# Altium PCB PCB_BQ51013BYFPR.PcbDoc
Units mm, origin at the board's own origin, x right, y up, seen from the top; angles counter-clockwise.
Board outline 45 x 20 mm, 2 copper layers (Top Layer, Bottom Layer); 61 components, 48 nets, 200 pads, 50 vias.
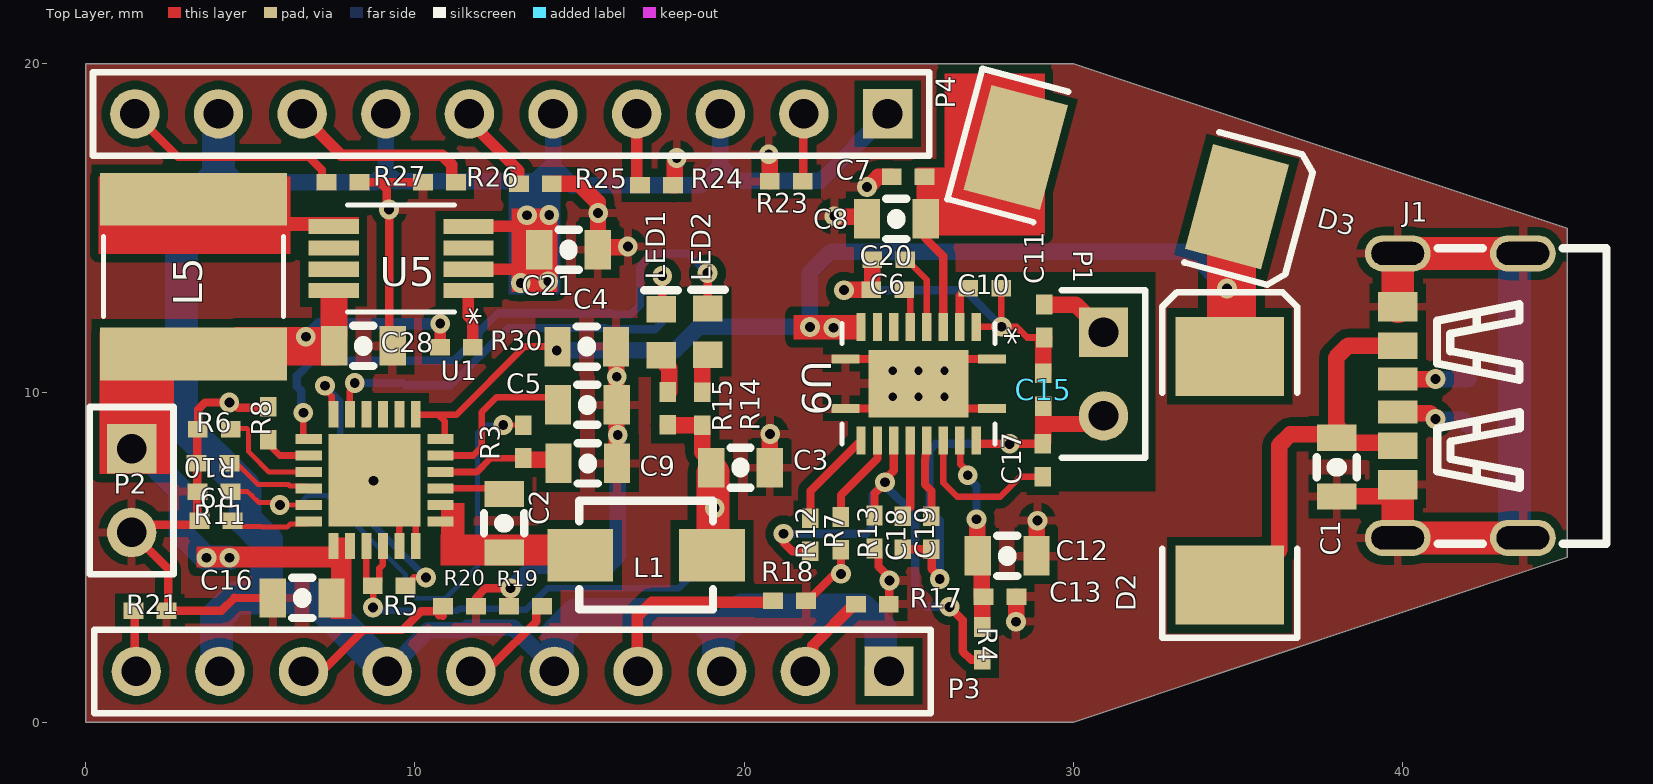
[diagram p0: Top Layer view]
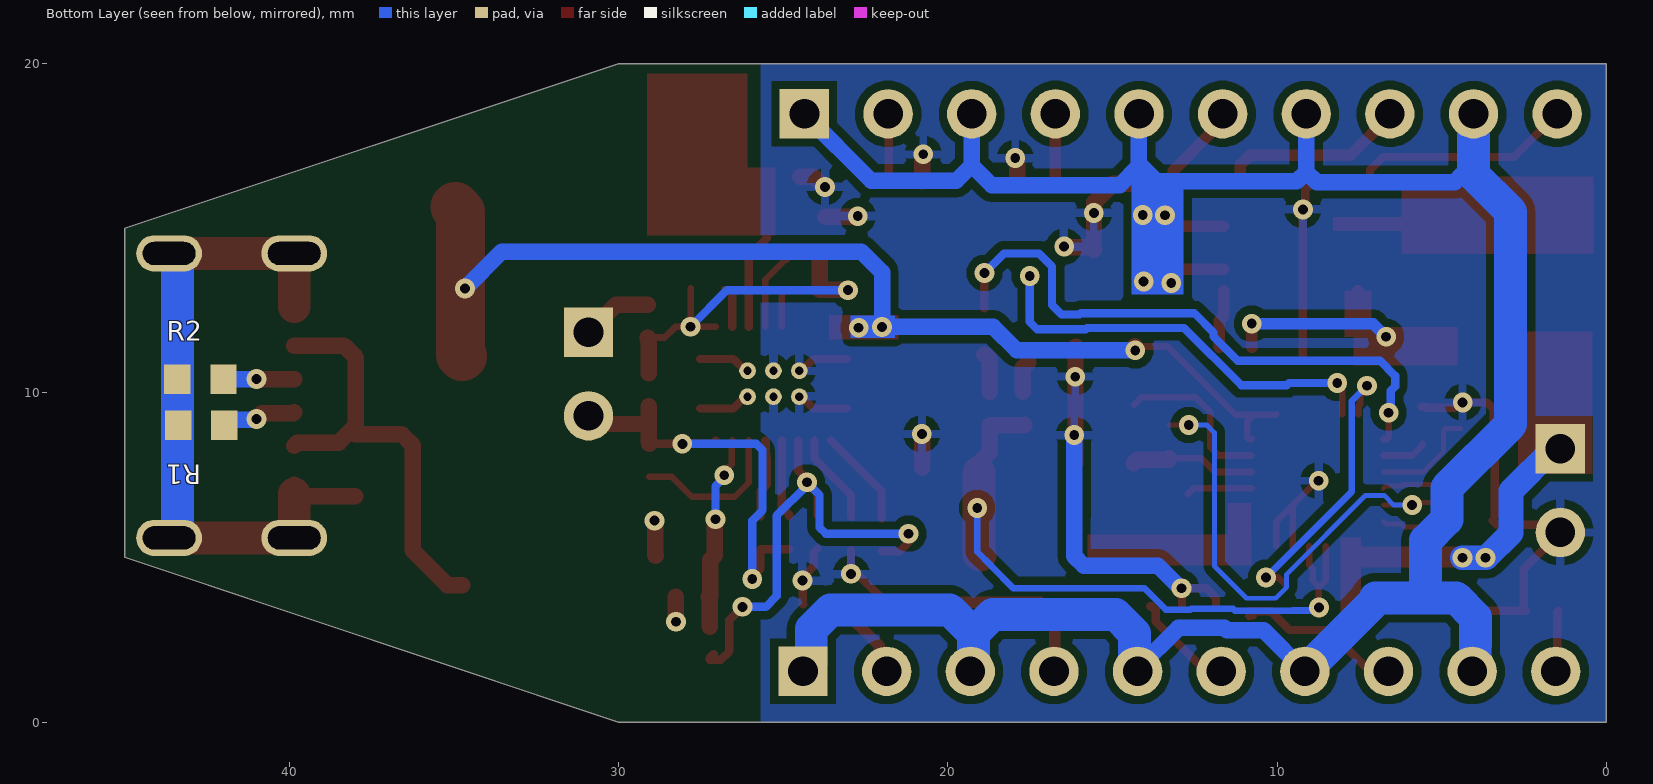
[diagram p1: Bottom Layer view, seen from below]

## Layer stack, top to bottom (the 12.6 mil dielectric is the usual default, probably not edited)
Top Solder: solder mask 0.0102, Solder Resist, Dk 3.5
Top Layer: signal copper 0.0356
Dielectric 1: dielectric 0.32, FR-4, Dk 4.8
Bottom Layer: signal copper 0.0356
Bottom Solder: solder mask 0.0102, Solder Resist, Dk 3.5

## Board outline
0,0 30,0 45,5 45,15 30,20 0,20

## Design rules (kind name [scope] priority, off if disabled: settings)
Clearance U1 [InComponent('U1')] p1: gap=0.254 ignorepadtopadclearanceinfootprint=FALSE except(0: Arc-Hole Track-Hole SMDPad-Hole THPad-Hole Via-Hole Fill-Hole Poly-Hole Region-Hole Text-Hole; 0.18: Arc-Arc Arc-Track Arc-SMDPad Track-Track Track-SMDPad SMDPad-SMDPad)
Clearance U5 [InComponent('U5')] p2: gap=0.254 ignorepadtopadclearanceinfootprint=FALSE except(0: Arc-Hole Track-Hole SMDPad-Hole THPad-Hole Via-Hole Fill-Hole Poly-Hole Region-Hole Text-Hole; 0.18: Arc-Arc Arc-Track Arc-SMDPad Arc-THPad Track-Track Track-SMDPad Track-THPad SMDPad-SMDPad SMDPad-THPad THPad-THPad; 0.2: Arc-Via Track-Via)
Clearance U2 [InComponent('U2')] p3: gap=0.254 ignorepadtopadclearanceinfootprint=FALSE except(0: Arc-Hole Track-Hole SMDPad-Hole THPad-Hole Via-Hole Fill-Hole Poly-Hole Region-Hole Text-Hole; 0.15: Arc-Arc Arc-Track Arc-SMDPad Arc-THPad Track-Track Track-SMDPad Track-THPad SMDPad-SMDPad SMDPad-THPad SMDPad-Via SMDPad-Fill SMDPad-Poly SMDPad-Region THPad-THPad Via-Via Via-Fill Via-Poly Via-Region Via-Text)
Clearance [All] p4: gap=0.254 ignorepadtopadclearanceinfootprint=FALSE except(0: Arc-Hole Track-Hole SMDPad-Hole THPad-Hole Via-Hole Fill-Hole Poly-Hole Region-Hole Text-Hole; 0.2: Arc-Arc Arc-Track Arc-SMDPad Track-Track Track-SMDPad SMDPad-SMDPad)
MinimumSolderMaskSliver USB-C-SMD_TYPE-C-USB-13 [HasFootprint('USB-C-SMD_TYPE-C-USB-13')] p1: minsoldermaskwidth=0
MinimumSolderMaskSliver RHL20_2P05X3P05 [HasFootprint('RHL20_2P05X3P05')] p2: minsoldermaskwidth=0
MinimumSolderMaskSliver [All] p3: minsoldermaskwidth=0.1
PolygonConnect [All] p1: connectstyle=Relief reliefconductorwidth=0.254 reliefentries=4 polygonreliefangle="90 Angle" airgapwidth=0.254
RoutingVias [All] p1: holewidth=0.711 width=1.27 viastyle="Through Hole" minholewidth=0.3 minwidth=0.6 maxholewidth=0.711 maxwidth=1.27
SilkToSilkClearance [All] p1: silktosilkclearance=0.1
SilkToSolderMaskClearance 0805-CAP [HasFootprint('0805-CAP')] p1: minsilkscreentomaskgap=0 clearancetoexposedcopper=TRUE
SilkToSolderMaskClearance 1608[0603]_LED [HasFootprint('1608[0603]_LED')] p2: minsilkscreentomaskgap=0 clearancetoexposedcopper=TRUE
SilkToSolderMaskClearance 0402-A [HasFootprint('0402-A')] p3: minsilkscreentomaskgap=0 clearancetoexposedcopper=TRUE
SilkToSolderMaskClearance [IsPad] p4: minsilkscreentomaskgap=0.1 clearancetoexposedcopper=TRUE
SolderMaskExpansion [All] p1: expansion=0.102 istentingtop=FALSE
Width [All] p1: maxlimit=1.5 minlimit=0.15 preferedwidth=0.254
27 further rules are at their usual default settings.

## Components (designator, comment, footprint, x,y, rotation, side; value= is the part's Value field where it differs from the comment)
C1 "Cap" 0805-CAP 38.025,7.76 r270 top value=1uF
C2 "Cap" 0805-CAP 12.737,6.056 r270 top value=47nF/25V
C3 "Cap" 0805-CAP 19.91,7.7 r180 top value=10uF/25V
C4 "Cap" 0805-CAP 15.24,11.38 r180 top value=1uF/25V
C5 "Cap" 0805-CAP 15.22,9.66 r0 top value=10uF/25V
C6 "Cap" 0402-A 24.361,13.128 r0 top value=22nF/25V
C7 "Cap" 0402-A 24.982,16.564 r0 top value=0.1uF/16V
C8 "Cap" 0805-CAP 24.605,15.306 r0 top value=10uF/16V
C9 "Cap" 0805-CAP 15.27,7.83 r180 top value=4.7uF/10V
C10 "Cap" 0402-A 27.31,13.17 r180 top value=10nF/25V
C11 "Cap" 0402-A 29.11,12.18 r270 top value=0.25uF/25V
C12 "Cap" 0805-CAP 28.01,5.02 r180 top value=10uF/16V
C13 "Cap" 0402-A 27.77,3.81 r180 top value=0.1uF/16V
C15 "Cap" 0402-A 29.085,10.092 r90 top value=2.5nF/25V
C16 "Cap" 0805-CAP 6.598,3.743 r180 top value=10uF/16V
C17 "Cap" 0402-A 29.07,7.95 r270 top value=10nF/25V
C18 "Cap" 0402-A 24.82,5.75 r90 top value=22nF/25V
C19 "Cap" 0402-A 25.691,5.749 r90 top value=0.47uF/25V
C20 "Cap" 0402-A 24.392,14.042 r0 top value=0.47uF/25V
C21 "Cap" 0805-CAP 14.65,14.37 r0 top value=10uF/25V
C28 "Cap" 0805-CAP 8.457,11.397 r180 top value=10uF/25V
D2 "SK56A-LTP" SMC 34.752,7.632 r90 top
D3 "SK56A-LTP" SMC 31.612,16.551 r345 top
J1 "USB 3.1 C 6PF COPY" USB-C-SMD_TYPE-C-USB-13 42,10 r90 top
L1 "1uH" IND-SMD_L4.1-W3.2 17.2,5.07 r0 top
L5 "4.7uH" IND_BOURNS_SRN50 3.28,13.53 r90 top value=SRN5020-4R7M
LED1 "LED0" 1608[0603]_LED 17.48,11.842 r90 top
LED2 "LED0" 1608[0603]_LED 18.9,11.86 r90 top
P1 "Header 2" HDR1X2 30.916,11.84 r270 top
P2 "Header 2" HDR1X2 1.401,8.3 r270 top
P3 "Header 10" HDR1X10 24.4,1.54 r180 top
P4 "Header 10" HDR1X10 24.358,18.472 r180 top
R1 "Res1" 1608[0603] 42.68,9.019 r0 bottom value=5.1k
R2 "Res1" 1608[0603] 42.702,10.407 r180 bottom value=5.1k
R3 "Res1" 0402-A 13.288,8.517 r270 top value=10k
R4 "Res1" 0402-A 27.24,2.39 r270 top value=20K
R5 "Res1" 0402-A 9.22,4.14 r180 top value=10K
R6 "Res1" 0402-A 3.908,8.893 r180 top value=10K
R7 "Res1" 0402-A 22.94,5.73 r270 top value=10k
R8 "Res1" 0402-A 5.548,9.074 r90 top value=158R
R9 "Res1" 0402-A 3.9,7 r0 top value=10k
R10 "Res1" 0402-A 3.87,7.855 r180 top value=221R
R11 "Res1" 0402-A 3.96,6.12 r180 top value=10K
R12 "Res1" 0402-A 22.003,5.689 r270 top value=66R
R13 "Res1" 0402-A 23.961,5.772 r270 top value=196R
R14 "Res1" 0402-A 18.726,9.517 r90 top value=10K
R15 "Res1" 0402-A 17.683,9.528 r90 top value=2.21K
R17 "Res1" 0402-A 23.896,3.577 r180 top value=1K
R18 "Res1" 0402-A 21.38,3.68 r180 top value=1K
R19 "Res1" 0402-A 13.364,3.514 r0 top value=1K
R20 "Res1" 0402-A 11.357,3.514 r180 top value=1K
R21 "Res1" 0402-A 1.957,3.386 r180 top value=1K
R23 "Res1" 0402-A 21.28,16.42 r0 top value=1K
R24 "Res1" 0402-A 17.34,16.3 r180 top value=1K
R25 "Res1" 0402-A 13.661,16.344 r180 top value=1K
R26 "Res1" 0402-A 10.75,16.39 r0 top value=1K
R27 "Res1" 0402-A 7.82,16.39 r180 top value=1K
R30 "Res1" 0402-A 11.263,11.378 r0 top value="1M Ohm"
U1 "BQ25616JRTWR" QFN50P400X400X80 8.772,7.354 r270 top
U5 "MCP1643T-I/MS" MSOP8_MC_MCH 9.585,14.078 r180 top
U9 "BQ51013BRHLR" RHL20_2P05X3P05 25.298,10.277 r270 top

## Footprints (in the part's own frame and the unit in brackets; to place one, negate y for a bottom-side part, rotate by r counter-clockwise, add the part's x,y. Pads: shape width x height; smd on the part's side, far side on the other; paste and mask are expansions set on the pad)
0402-A [mm] "Chip Inductor, Body 1.0x0.5mm, IPC High Density"
  rect 0.6x0.5 smd: 1(-0.5,0) 2(0.5,0)
  body extent -0.55,-0.3 0.55,0.3, height 0.55
0805-CAP [mil]
  rect 31.5x47.2 smd: 1(-34.25,-1) 2(35.75,-1)
  silkscreen extent -11,-25 13,23
1608[0603] [mm] "Chip Capacitor, Body 1.6x0.8mm, IPC High Density"
  rect 0.8x0.9 smd: 1(-0.7,0) 2(0.7,0)
  body extent -0.87,-0.48 0.87,0.48, height 1.3
1608[0603]_LED [mm] "Chip Capacitor, Body 1.6x0.8mm, IPC High Density"
  rect 0.8x0.9 smd: 1(-0.7,0) 2(0.7,0)
  silkscreen extent 1.27,-0.51 1.27,0.51, body extent -0.87,-0.48 0.87,0.48, height 1.3
HDR1X2 [mm] "Connector; Header; 2 Position"
  rect 1.5x1.5 hole 0.9: 1(0,0)
  round 1.5 hole 0.9: 2(2.54,0)
  silkscreen extent -1.27,-1.27 3.81,1.27
HDR1X10 [mm] "Connector; Header; 10 Position"
  rect 1.5x1.5 hole 0.9: 1(0,0)
  round 1.5 hole 0.9: 2(2.54,0) 3(5.08,0) 4(7.62,0) 5(10.16,0) 6(12.7,0) 7(15.24,0) 8(17.78,0) 9(20.32,0) 10(22.86,0)
  silkscreen extent -1.27,-1.27 24.13,1.27
IND-SMD_L4.1-W3.2 [mm]
  rect 2x1.6 smd: 1(-2.175,0) 2(1.825,0)
  silkscreen extent -2.21,-1.65 1.86,1.65
IND_BOURNS_SRN50 [mil]
  rect 63x224 smd: 1(-92.5,0) 2(92.5,0)
  silkscreen extent -48,-108 48,108
MSOP8_MC_MCH [mil]
  rect 60x18 smd: 1(-80.5,38.39) 2(-80.5,12.8) 3(-80.5,-12.8) 4(-80.5,-38.39) 5(80.5,-38.39) 6(80.5,-12.8) 7(80.5,12.8) 8(80.5,38.39)
  silkscreen extent -64,-64 64,64
QFN50P400X400X80 [mil]
  rect 31.5x11.81 smd: 1(-78.43,49.53) 2(-78.43,29.85) 3(-78.43,10.15) 4(-78.43,-9.52) 5(-78.43,-29.21) 6(-78.43,-48.89) 13(79.05,-48.89) 14(79.05,-29.21) 15(79.05,-9.52) 16(79.05,10.15) 17(79.05,29.85) 18(79.05,49.53)
  rect 11.81x31.5 smd: 7(-48.9,-78.42) 8(-29.22,-78.42) 9(-9.53,-78.42) 10(10.15,-78.42) 11(29.84,-78.42) 12(49.52,-78.42) 19(49.52,79.06) 20(29.84,79.06) 21(10.15,79.06) 22(-9.53,79.06) 23(-29.22,79.06) 24(-48.9,79.06)
  rect 110.24x110.24 smd: 25(0.31,0.32)
RHL20_2P05X3P05 [mm]
  rect 0.28x0.85 smd: 1(-0.75,2.225) 10(-0.75,-2.225) 11(0.75,-2.225) 20(0.75,2.225)
  rect 0.85x0.28 smd: 2(-1.725,1.75) 3(-1.725,1.25) 4(-1.725,0.75) 5(-1.725,0.25) 6(-1.725,-0.25) 7(-1.725,-0.75) 8(-1.725,-1.25) 9(-1.725,-1.75) 12(1.725,-1.75) 13(1.725,-1.25) 14(1.725,-0.75) 15(1.725,-0.25) 16(1.725,0.25) 17(1.725,0.75) 18(1.725,1.25) 19(1.725,1.75)
  rect 2.05x3.05 smd: 21(0,0)
  round 0.508 hole 0.254 mask-25.4: 22(-0.394,-0.787) 23(-0.394,0) 24(-0.394,0.787) 25(0.394,-0.787) 26(0.394,0) 27(0.394,0.787)
  silkscreen extent -1.83,-2.32 1.83,2.32
SMC [mm] "DO-214-AB/SMC; 2 C-Bend Leads; Body 7.9 x 5.9 mm, inc. leads (LxW)"
  rect 2.4x3.3 smd: 1(-3.475,0) 2(3.475,0)
  silkscreen extent -5.07,-2.05 5.43,2.05
USB-C-SMD_TYPE-C-USB-13 [mm]
  oval 1.1x2 hole 0.7 slot 1.6 at 90 deg: 0(-4.407,-1.652) 0(-4.407,2.148) 0(4.233,-1.652) 0(4.233,2.148)
  rect 0.7x1.2 smd: A5(-0.587,2.146) B5(0.413,2.146)
  rect 0.8x1.2 smd: A9(-1.607,2.148) B9(1.433,2.15)
  rect 0.9x1.2 smd: A12(-2.787,2.148) B12(2.613,2.148)
  silkscreen extent -4.59,-4.19 4.39,0.95

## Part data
C1 C2 C3 C4 C5 C6 C7 C8 C9 C10 C11 C12 C13 C15 C16 C17 C18 C19 C20 C21 C28: "Capacitor"
D2 D3: library part Diode, "DIODE SCHOTTKY 5A 60V SMA"
L1: library part Inductor
L5: library part SRN5020-4R7M, Mfr_Name="Bourns Electronics"
P1 P2: "Header, 2-Pin"
P3 P4: "Header, 10-Pin"
R1 R2 R3 R4 R5 R6 R7 R8 R9 R10 R11 R12 R13 R14 R15 R17 R18 R19 R20 R21 R23 R24 R25 R26 R27 R30: "Resistor"
U5: Mfr_Name=Microchip
U9: Mfr_Name="Texas Instruments"

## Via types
v1: diameter 0.6, hole 0.3, Top Layer to Bottom Layer, tented both sides, 39 vias
v2: diameter 0.6, hole 0.3, Top Layer to Bottom Layer, 11 vias

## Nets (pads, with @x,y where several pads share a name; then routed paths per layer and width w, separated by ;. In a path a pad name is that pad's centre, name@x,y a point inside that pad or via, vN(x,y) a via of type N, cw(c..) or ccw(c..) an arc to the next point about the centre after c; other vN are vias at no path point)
+5: C21.1 P3.1 P3.3 P3.5 P3.7 P3.9 P4.1 P4.3 P4.5 P4.7 P4.9 U5.2 U5.4 | length 77.2
  Top Layer w0.35: U5.2 13.388,13.753 13.78,14.145 C21.1 13.78,14.544 13.271,15.053 U5.4
  Bottom Layer w0.5: 4.384,16.626 4.61,16.4 8.805,16.4 9.118,16.713 ; P4.7 9.118,16.713 ; P3.7 10.414,2.794 11.534,2.794 11.6,2.86 13,2.86 14.24,1.62 P3.5 ; P4.5 14.198,16.958 ; P4.3 19.278,16.912 ; P4.1 22.326,16.44 19.75,16.44 19.278,16.912 ; 9.118,16.713 9.411,16.42 13.66,16.42 14.198,16.958 ; 14.198,16.958 14.198,16.892 14.784,16.306 18.672,16.306 19.278,16.912
  Bottom Layer w1: P4.9 4.038,16.626 2.911,15.499 2.911,9.05 4.848,7.113 4.848,6.152 5.49,5.51 5.49,3.77 ; P3.9 3.984,1.636 3.984,2.351 3.98,2.356 3.98,3.184 4.566,3.77 5.49,3.77 ; P3.7 7.019,3.681 7.019,3.77 5.49,3.77 ; P3.5 14.336,1.636 14.336,2.696 14.91,3.27 18.639,3.27 19.224,2.684 ; P3.3 19.224,1.636 19.224,2.684 ; P3.1 24.15,1.79 24.15,2.824 23.564,3.41 19.95,3.41 19.224,2.684
  other v1: 13.217,13.335
  other v2: 14.056,13.377 13.405,15.392 14.082,15.397
+VBAT: C16.1 C28.2 L5.1 P2.1 R30.1 U1.13 U1.14 U5.8 | length 15.2
  Top Layer w0.35: v2(3.67,4.99) 3.68,5 4.36,5 v2@4.37,5.01 ; v2(4.37,4.99) 5.767,4.99 5.787,5.01 7.634,5.01 U1.13@7.634,5.023 ; v1(6.691,11.702) 6.973,11.42 7.1,11.42 C28.2@7.505,11.825 ; U5.8 U5.8@7.549,13.094 ; R30.1 10.768,11.383 10.768,12.096 v1(10.772,12.101)
  Bottom Layer w0.35: v1(6.691,11.702) 7.089,12.101 v1(10.772,12.101)
  Bottom Layer w0.75: P2.1 1.62,8.3 2.901,7.019 2.901,5.739 3.65,4.99 v2(3.67,4.99) v2(4.37,4.99)
C_VCC: C4.2 D2.2 D3.2 U1.1 U1.24 U9.9 | length 33.9
  Top Layer w0.2: U1.1 10.046,9.33 10.72,9.33 ; U1.24 10.86,8.596 10.91,8.646 10.91,9.14 10.72,9.33 ; C4.2 C4.2 13.335,11.405 11.26,9.33 10.72,9.33
  Top Layer w0.5: v1(14.31,11.29) 14.33,11.31 C4.2 C4.2@14.33,11.407
  Top Layer w1.5: D2.2 34.802,11.157 34.802,15.485 D3.2
  Bottom Layer w0.5: v1(14.31,11.29) 15.801,11.29 16.467,11.29 17.912,11.29 18.623,12.001 21.999,12.001 v1(22,12) 22,13.66 22.63,14.29 33.55,14.29 v1(34.67,13.17)
  other v1: 22.71,11.977
FOD: R4.2 R12.2 R13.1 U9.14 | length 15.4
  Top Layer w0.25: v1(21.2,5.72) 21.2,5.45 21.461,5.189 R12.2 ; R13.1 23.961,6.947 24.282,7.268 v1(24.282,7.282) ; v1@24.28,7.35 24.28,7.375 24.548,7.643 U9.14 ; v1(26.24,3.5) 26.64,3.1 26.64,2.15 26.9,1.89 R4.2 27.24,1.94 R4.2@27.115,2.065
  Bottom Layer w0.25: v1(21.2,5.72) 23.71,5.72 23.9,5.91 23.9,6.9 v1(24.282,7.282) 24.282,7.187 25.2,6.269 25.2,3.83 25.53,3.5 v1(26.24,3.5)
GND: C1.2 C3.1 C4.1 C5.2 C7.1 C8.1 C9.1 C12.1 C13.1 C16.2 C21.2 C28.1 J1.0 J1.A12 J1.B12 P2.2 R1.2 R2.1 R6.2 R7.2 R8.2 R9.1 R10.2 R11.2 R13.2 R17.1 R18.1 R19.1 R20.1 R21.1 R23.1 R24.1 R25.1 R26.1 R27.1 U1.17 U1.18 U1.25 U9.1 U9.10 U9.11 U9.20 U9.21 U9.22 U9.23 U9.24 U9.25 U9.26 U9.27 | length 80.8
  Top Layer w0.2: U1.25 U1.25@9.53,6.596 ; U1.17 U1.25@9.53,6.596 ; U1.18 10.03,6.096 U1.25@9.53,6.596
  Top Layer w0.25: v1@22.94,4.503 R7.2@22.94,5.23 ; U9.11 24.085,9.527 24.441,9.884 U9.25 ; U9.10 24.085,11.027 24.441,10.671 U9.22 ; R13.2 24.086,5.147 24.086,4.727 24.417,4.396 v2(24.417,4.302) ; U9.27 26.156,9.884 26.512,9.527 U9.20 ; U9.24 26.156,10.671 26.512,11.027 U9.1
  Top Layer w0.254: R11.2@3.389,6.261 3.389,8.031 3.394,8.036 3.394,8.988 3.422,9.016 3.422,9.497 3.633,9.707 v1(4.367,9.707) 4.461,9.707 4.626,9.542 5.484,9.542 5.515,9.573 R8.2@5.607,9.573 ; R11.2 3.337,5.997 1.638,5.997 P2.2 2.512,4.65 2.512,3.441 R21.1 4.13,3.386 4.518,3.774 4.524,3.768 C16.2 ; R27.1 8.93,16.39 ; C28.1@9.218,11.123 v1(9.218,15.564) 9.152,15.63 9.152,16.168 8.93,16.39 ; R26.1 8.93,16.39 ; R20.1 11.858,3.77 12.153,4.065 v2(12.909,4.065) 12.893,4.05 R19.1@12.893,3.514 ; R18.1 21.93,3.68 v1@22.702,4.452 ; R17.1 24.407,3.588 24.407,4.291 v2(24.417,4.302)
  Top Layer w0.5: R25.1 14.996,16.344 15.55,15.79 15.55,15.482 v1(15.569,15.463) 15.564,15.457 C21.2@15.564,14.35 ; C21.2 C21.2@15.564,14.35 ; C4.1 16.125,11.39 16.125,7.87 C9.1 ; v1(16.47,14.44) 16.451,14.421 15.634,14.421 C21.2@15.564,14.35 ; R24.1 17.89,16.3 17.89,17.036 17.955,17.101 v1(17.955,17.128) ; v1(20.75,17.244) 20.75,17.217 20.78,17.187 R23.1 ; C3.1 20.786,7.732 20.786,8.746 v1(20.793,8.753) ; v1(22.738,15.365) 22.75,15.352 23.71,15.352 C8.1@23.722,15.339 ; v1(23.735,16.252) 23.762,16.252 24.074,16.564 C7.1 ; v1(28.261,3.046) 28.265,3.051 28.265,3.81 C13.1 ; C12.1 28.894,5.06 28.894,6.103 v1(28.909,6.117) ; C1.2 39.774,6.852 J1.A12@39.852,6.93 ; J1.A12@39.729,7.09 J1.A12
  Top Layer w1: J1.0@39.375,14.233 39.852,14.233 J1.0@43.652,14.233 ; J1.0@39.852,5.593 J1.A12@39.852,6.93 ; J1.B12 J1.0@39.852,14.233 ; J1.0@39.852,5.593 J1.0@43.652,5.593
  Bottom Layer w0.5: v2(12.909,4.065) 12.936,4.065 13.62,4.75 15.877,4.75 16.17,5.043 16.17,6.22 16.164,6.226 v2(16.164,8.716)
  Bottom Layer w1: J1.0@43.652,5.593 43.448,5.593 43.402,5.639 R2.1 43.402,14.187 43.448,14.233 J1.0@43.652,14.233
  other v1: 22.941,4.502
  other v2: 8.74,7.33 16.134,10.486
NetC1_1: C1.1 D2.1 J1.A9 J1.B9 | length 13.2
  Top Layer w0.5: D2.1 35.202,4.157 36.26,5.216 36.26,5.645 36.25,5.655 36.25,8.4 36.59,8.74 C1.1@38.005,8.74 ; J1.B9 38.343,11.433 37.98,11.07 37.98,9.01 38.502,8.488 39.758,8.488 J1.A9
NetC2_1: C2.1 U1.21 | length 2
  Top Layer w0.2: U1.21 12.542,7.096 C2.1
NetC2_2: C2.2 L1.1 U1.19 U1.20
NetC5_1: C5.1 U1.23 | length 5
  Top Layer w0.2: U1.23 11.776,8.096 12.033,8.353 12.033,9.413 12.49,9.87 14.115,9.87 C5.1
NetC6_1: C6.1 C10.1 C11.2 C15.2 C20.1 U9.2 | length 11.5
  Top Layer w0.2: U9.2 28.278,12.002 28.6,11.68 C11.2 ; C10.1 27.81,12.012 v1(27.816,12.006)
  Top Layer w0.5: v1(23.033,13.117) 23.045,13.128 C6.1 23.892,13.128 C20.1 ; C15.2 29.085,11.605 29.11,11.63 C11.2
  Bottom Layer w0.25: v1(23.033,13.117) 26.705,13.117 v1(27.816,12.006)
NetC6_2: C6.2 U9.6 | length 1.2
  Top Layer w0.2: C6.2 24.898,13.128 25.048,12.978 U9.6
NetC7_2: C7.2 C8.2 D3.1 U9.4 | length 3.6
  Top Layer w0.25: C8.2@25.5,15.339 25.5,14.704 26.048,14.156 U9.4
NetC10_2: C10.2 U9.3 | length 1.3
  Top Layer w0.15: C10.2@26.548,12.958 26.76,13.17 C10.2
  Top Layer w0.25: U9.3 C10.2@26.548,12.958
NetC11_1: C11.1 P1.1 | length 2.2
  Top Layer w0.5: C11.1 30.076,12.68 P1.1
NetC12_2: C12.2 C13.2 R4.1 U9.18 | length 6
  Top Layer w0.2: U9.18 26.571,8.529 26.571,7.827 26.793,7.605 v1(26.793,7.497)
  Top Layer w0.5: v1(27.06,6.16) 27.079,6.141 27.079,5.068 C12.2 27.22,4.927 27.22,3.81 C13.2@27.24,3.81 ; R4.1 C13.2@27.24,3.81 ; C13.2 C13.2@27.24,3.81
  Bottom Layer w0.25: v1(26.793,7.497) 26.793,7.429 27.06,7.163 v1(27.06,6.16)
NetC15_1: C15.1 C17.1 C18.1 C19.1 P1.2 U9.19 | length 13.6
  Top Layer w0.25: C18.1 C19.1@25.691,5.25 ; C19.1 25.697,5.244 25.697,4.656 25.942,4.41 v1(25.942,4.347) ; U9.19 27.048,8.465 27.063,8.45 v1(28.067,8.45) C17.1
  Top Layer w0.5: C17.1 29.07,8.5 29.085,8.515 29.085,9.053 ; C15.1 29.085,9.053 ; P1.2 30.668,9.053 29.085,9.053
  Bottom Layer w0.25: v1(25.942,4.347) 25.942,6.119 25.63,6.431 25.63,8.26 25.82,8.45 v1(28.067,8.45)
NetC17_2: C17.2 U9.17 | length 4.7
  Top Layer w0.2: U9.17 26.048,7.267 26.472,6.843 27.783,6.843 28.39,7.45 C17.2
NetC18_2: C18.2 U9.15 | length 2.4
  Top Layer w0.25: C18.2 24.82,6.3 25.046,6.526 25.046,8.55 U9.15
NetC19_2: C19.2 U9.16 | length 2.4
  Top Layer w0.25: U9.16 25.533,8.537 25.533,8.149 25.513,8.129 25.513,7.993 25.496,7.975 25.496,7.218 25.691,7.023 C19.2
NetC20_2: C20.2 U9.5 | length 2.3
  Top Layer w0.2: C20.2 24.942,14.042 25.548,13.436 U9.5
NetJ1_A5: J1.A5 R1.1 | length 2.3
  Top Layer w0.5: J1.A5 39.887,9.38 40.84,9.38 40.94,9.28 v1@40.99,9.28
  Bottom Layer w0.5: v1(40.996,9.206) 41.015,9.186 41.83,9.186 41.98,9.036 R1.1
NetJ1_B5: J1.B5 R2.2 | length 2.2
  Top Layer w0.5: J1.B5 40.996,10.413 v1(41.003,10.42)
  Bottom Layer w0.5: v1(41.003,10.42) 41.009,10.413 41.995,10.413 R2.2
NetL5_2: L5.2 U5.5
NetLED1_1: LED1.1 R15.2 | length 1
  Top Layer w0.5: LED1.1@17.564,10.923 17.723,10.764 R15.2@17.723,10.028
NetLED1_2: LED1.2 U1.5 | length 13.8
  Top Layer w0.2: U1.5 8.03,10.043 8.176,10.189 v1(8.176,10.298)
  Top Layer w0.25: LED1.2@17.515,12.324 v1(17.515,13.551)
  Bottom Layer w0.25: v1(8.176,10.298) 9.639,10.298 9.708,10.229 11.089,10.229 12.829,11.969 15.775,11.969 15.814,11.93 17.29,11.93 17.515,12.155 v1(17.515,13.551)
NetLED2_1: LED2.1 R14.2 | length 1.2
  Top Layer w0.5: R14.2 18.726,11.01 18.876,11.16 LED2.1
NetLED2_2: LED2.2 U1.7 | length 18.3
  Top Layer w0.2: v1(6.615,9.395) 6.615,8.646 6.665,8.596 U1.7
  Top Layer w0.25: v1(18.89,13.64) 18.9,13.63 LED2.2
  Bottom Layer w0.25: v1(6.615,9.395) 6.548,9.462 6.548,10.064 6.417,10.195 6.417,10.517 6.877,10.977 11.2,10.977 11.932,11.708 11.932,11.832 12.519,12.419 15.962,12.419 16.001,12.38 16.552,12.38 16.836,12.664 16.836,13.832 17.234,14.23 18.3,14.23 v1(18.89,13.64)
NetP3_2: P3.2 R17.2 | length 2.7
  Top Layer w0.35: P3.2 22.08,1.76 22.08,2.311 23.346,3.577 R17.2
NetP3_4: P3.4 R18.2 | length 6
  Top Layer w0.35: P3.4 16.76,1.56 16.76,3.21 17.19,3.64 20.84,3.64 R18.2
NetP3_6: P3.6 R19.2 | length 3.2
  Top Layer w0.254: P3.6 11.938,1.778 12.411,1.778 13.691,3.059 13.691,3.391 13.814,3.514 R19.2
NetP3_8: P3.8 R20.2 | length 5.2
  Top Layer w0.25: P3.8 7.18,1.54 8.44,2.8 9.62,2.8 10.184,3.364 10.857,3.364 10.732,3.239
NetP3_10: P3.10 R21.2 | length 1.9
  Top Layer w0.254: R21.2 1.498,3.344 1.498,1.582 P3.10
NetP4_2: P4.2 R23.2 | length 2.1
  Top Layer w0.25: R23.2 21.799,16.439 21.799,18.453 P4.2
NetP4_4: P4.4 R24.2 | length 2.2
  Top Layer w0.35: P4.4 16.738,16.375 16.813,16.3 R24.2
NetP4_6: P4.6 R25.2 | length 2.8
  Top Layer w0.35: P4.6 11.878,18.252 11.878,18.026 13.161,16.743 R25.2
NetP4_8: P4.8 R26.2 | length 5.8
  Top Layer w0.35: P4.8 6.578,18.412 7.772,17.218 10.832,17.218 11.125,16.925 11.125,16.465 11.2,16.39 R26.2
NetP4_10: P4.10 R27.2 | length 6.8
  Top Layer w0.254: P4.10 2.808,17.162 6.788,17.162 7.18,16.77 7.18,16.513 7.303,16.39 R27.2
NetR3_1: R3.1 R9.2 U1.11 | length 16.1
  Top Layer w0.15: R9.2 4.925,7 5.05,6.875 5.253,6.672 5.694,6.672 5.771,6.595 v1@5.771,6.587 ; v1@5.772,6.589 6.455,6.589 U1.11 ; v2(12.687,9.022) 13.284,9.022 R3.1
  Bottom Layer w0.15: v1(5.902,6.589) 6.458,6.589 6.752,6.883 7.316,6.883 9.711,4.489 9.711,4.096 10.046,3.761 10.931,3.761 11.91,4.74 11.91,8.79 12.142,9.022 v2(12.687,9.022)
NetR5_1: R5.1 U1.6 | length 8.8
  Top Layer w0.2: v1(7.27,10.216) 7.27,10.108 7.48,9.898 7.48,9.646 7.53,9.596 U1.6 ; R5.1 9.97,4.39 v1(10.34,4.39)
  Bottom Layer w0.2: v1(7.27,10.216) 7.74,9.746 7.74,6.99 v1(10.34,4.39)
NetR6_1: R6.1 U1.9 | length 3.3
  Top Layer w0.15: R6.1@4.41,8.91 4.9,8.91 4.953,8.857 4.953,8.21 5.028,8.136 ; 5.029,8.136 5.569,7.596 U1.9
NetR7_1: R7.1 U9.13 | length 2.8
  Top Layer w0.25: R7.1 22.94,6.9 24.048,8.008 U9.13
NetR8_1: R8.1 U1.8 | length 1.4
  Top Layer w0.2: R8.1@5.587,8.458 5.587,8.408 5.899,8.096 U1.8
NetR10_1: R10.1 U1.10 | length 2.8
  Top Layer w0.15: R10.1@4.378,8.02 4.428,8.02 5.231,7.218 6.162,7.218 6.209,7.171 6.705,7.171 U1.10
NetR11_1: R11.1 U1.12 | length 2.5
  Top Layer w0.15: R11.1 4.635,5.945 5.34,5.945 5.365,5.92 6.122,5.92 6.223,6.021 6.705,6.021 U1.12
NetR12_1: R12.1 U9.12 | length 3
  Top Layer w0.25: R12.1 22.02,6.206 22.02,7.024 U9.12
NetR30_2: R30.2 U5.1 | length 1.8
  Top Layer w0.35: U5.1 11.63,12.318 11.763,12.185 R30.2
REGN: C9.2 R3.2 U1.22 | length 3.9
  Top Layer w0.2: U1.22 11.886,7.596 12.307,8.017 R3.2
  Top Layer w0.5: R3.2 13.288,7.967 14.25,7.967 C9.2
SYS: C3.2 L1.2 R5.2 R14.1 R15.1 U1.15 U1.16 | length 21.2
  Top Layer w0.2: U1.15 8.53,4.29 8.68,4.14 R5.2 ; v1(8.732,3.479) 8.732,4.128 R5.2 ; U1.16 9.03,4.775 8.92,4.666 8.92,4.29 8.77,4.14 R5.2
  Top Layer w0.254: L1.2@18.962,5.007 L1.2
  Top Layer w0.5: R15.1 17.683,9.017 R14.1 18.726,8.2 19.054,7.873 C3.2@19.054,7.575 ; L1.2@18.888,5.007 L1.2@18.962,5.007
  Top Layer w1: L1.2 19.054,5.099 C3.2@19.054,7.575
  Bottom Layer w0.2: v1(8.732,3.479) 8.822,3.389 9.524,3.389 9.527,3.386 11.288,3.386 11.342,3.44 12.609,3.44 12.638,3.411 13.381,3.411 14.04,4.07 18.02,4.07 18.68,4.73 18.68,4.743 19.11,5.173 v1(19.11,6.5)
pads on no net: U1.2 U1.3 U1.4 U5.3 U5.6 U5.7 U9.7 U9.8

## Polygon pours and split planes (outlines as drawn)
GND on Top Layer "GND_L01_P001" (solid, pour order 1): 0,0 30,0 45,5 45,15 30,20 0,20
GND on Bottom Layer "GND_L02_P000" (solid, pour order 0): 0,20 0,0 25.681,0 25.689,-0.007 25.692,-0.005 25.692,19.991 25.683,20

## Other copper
Top Layer:
  rectangle net C_VCC: 21.5,11.62 23.61,12.37
  rectangle net NetC7_2: 26.09,14.78 29.135,19.7
  rectangle net NetC7_2: 25.23,14.78 29.135,16.85
  rectangle net NetC2_2: 10.782,4.753 15.754,5.7
  rectangle net NetC2_2: 10.8,4.773 11.51,6.658
  rectangle net +VBAT: 7.14,11.69 7.95,13.103
  rectangle net +VBAT: 4.52,10.833 7.68,12
  rectangle net +5: 12.93,13.06 14.33,15.59
  rectangle net NetL5_2: 5.76,14.91 8.299,15.334
  rectangle net +VBAT: 3.37,4.69 7.634,5.33
  rectangle net +VBAT: 7.459,3.126 8.082,5.609
  rectangle net +VBAT: 0.431,7.54 2.69,11.855
  pour cut-out: 26.435,13.674 32.5,13.674 32.5,7 26.432,7 26.434,7.002 26.434,13.674
  region net NetL5_2: 6.21,14.22 0.4,14.22 0.4,16.56 6.21,16.56
Bottom Layer:
  rectangle net C_VCC: 21.601,11.665 22.961,12.347
  rectangle net +5: 12.84,12.98 14.42,16.68

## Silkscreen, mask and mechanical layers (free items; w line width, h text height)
Mechanical 1:
  the board outline again, w0.254

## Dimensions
45,5 to 30,0 on Mechanical 2
30,20 to 45,15 on Mechanical 2
45,15 to 45,5 on Mechanical 2
0,0 to 30,0 on Mechanical 2
0,20 to 0,0 on Mechanical 2
0,20 to 30,20 on Mechanical 2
